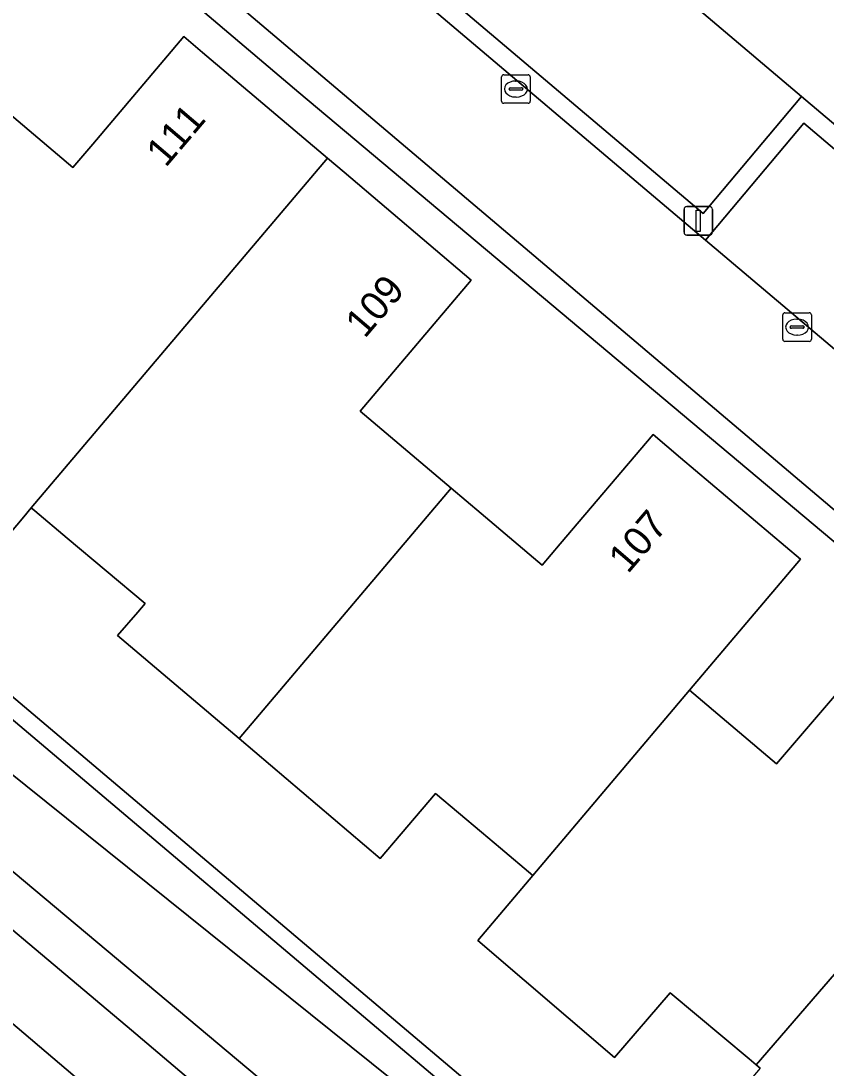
# Model space of a CAD drawing. Extents: x 156412 to 157779, y 382335 to 383768.
# Drawn here: x 156946.93 to 156975.09, y 382535.79 to 382572.44 of the extents above; entities that cross this region are included whole.
import ezdxf

# ---------------------------------------------------------------- set-up
doc = ezdxf.new("R2010")
doc.units = 0
for name, color, linetype in [('IMGEO_Erf', 7, 'Continuous'), ('IMGEO_Groenvoorziening', 7, 'Continuous'), ('IMGEO_Haag', 7, 'Continuous'), ('IMGEO_Kolk', 7, 'Continuous'), ('IMGEO_Lichtmast', 7, 'Continuous'), ('IMGEO_Oever', 7, 'Continuous'), ('IMGEO_Pand', 7, 'Continuous'), ('IMGEO_Pand_nummerreeks', 7, 'Continuous'), ('IMGEO_Parkeervlak_open', 7, 'Continuous'), ('IMGEO_Rijbaan_lokaal_open', 7, 'Continuous'), ('IMGEO_Voetpad_open', 7, 'Continuous'), ('IMGEO_Waterloop', 7, 'Continuous')]:
    doc.layers.add(name, color=color, linetype=linetype)

msp = doc.modelspace()

# ---------------------------------------------------------------- linework, layer by layer
at = {"layer": 'IMGEO_Erf'}
for points in [[(157032.018, 382606.037), (157033.314, 382604.947), (157032.946, 382604.52), (157041.703, 382597.123), (157047.972, 382604.539), (157048.196, 382604.798), (157060.586, 382619.348), (157029.826, 382645.416), (156987.205, 382681.476), (156986.214, 382682.315), (156984.143, 382684.067), (156942.915, 382635.543), (156901.626, 382586.899), (156977.949, 382522.266), (156980.608, 382525.348), (156995.995, 382543.705), (156987.057, 382551.292)], [(156985.096, 382551.062), (156984.751, 382551.362), (156982.188, 382548.489), (156956.652, 382569.938), (156926.325, 382595.645), (156936.95, 382608.202), (156992.775, 382560.898), (156990.241, 382557.869), (156990.622, 382557.547)], [(156946.128, 382569.514), (156948.739, 382567.303), (156949.437, 382568.128), (156952.622, 382571.89), (156953.277, 382571.336), (156957.652, 382567.631), (156958.23, 382567.141), (156962.681, 382563.371), (156958.797, 382558.785), (156961.981, 382556.088), (156963.032, 382555.198), (156965.165, 382553.392), (156965.795, 382554.134), (156969.046, 382557.96), (156970.005, 382557.148), (156974.199, 382553.6), (156970.317, 382549.012), (156973.355, 382546.442), (156976.505, 382550.113), (156977.268, 382551.003), (156982.117, 382546.872), (156985.394, 382550.663), (156991.994, 382545.054), (156977.449, 382527.892)], [(156972.786, 382535.791), (156972.643, 382535.912), (156972.401, 382536.118), (156969.636, 382538.426), (156967.697, 382536.158), (156962.908, 382540.256), (156964.837, 382542.536), (156963.701, 382543.486), (156963.042, 382544.044), (156961.425, 382545.397), (156960.231, 382543.992), (156959.498, 382543.128), (156954.557, 382547.323), (156950.307, 382550.931), (156951.01, 382551.743), (156951.277, 382552.051), (156948.547, 382554.34), (156947.415, 382555.289), (156947.289, 382555.394), (156947.03, 382555.088), (156946.346, 382554.281)]]:
    msp.add_lwpolyline(points, dxfattribs=at)
at = {"layer": 'IMGEO_Groenvoorziening'}
for points in [[(156975.056, 382695.155), (156974.339, 382694.322), (156973.623, 382693.49), (156976.375, 382691.256), (156980.161, 382688.027), (156981.799, 382686.639), (156940.772, 382637.701), (156895.927, 382586.799), (156991.196, 382510.245), (156996.315, 382506.277), (156998.499, 382508.854)], [(157000.033, 382540.277), (156996.653, 382543.146), (156996.633, 382543.163), (156996.382, 382542.842), (156978.115, 382521.345), (156900.751, 382586.801), (156984.174, 382685.107)], [(156982.943, 382562.429), (156974.229, 382569.798), (156970.799, 382565.697), (156960.828, 382574.147), (156964.288, 382578.231), (156963.775, 382578.659), (156959.881, 382574.086), (156970.874, 382564.762), (156974.312, 382568.857), (156982.37, 382562.02), (156978.916, 382557.959)]]:
    msp.add_lwpolyline(points, dxfattribs=at)
for points in [[(156895.927, 382586.799), (156940.772, 382637.701), (156981.799, 382686.639), (156980.161, 382688.027), (156972.98, 382679.885), (156951.724, 382654.157), (156930.591, 382629.503), (156894.284, 382586.815), (156936.438, 382551.218), (156974.72, 382519.113), (156990.891, 382505.312), (156993.571, 382503.037), (156996.315, 382506.277), (156991.196, 382510.245)], [(156984.143, 382684.067), (156986.214, 382682.315), (156986.444, 382682.612), (156986.719, 382682.899), (156984.174, 382685.107), (156900.751, 382586.801), (156978.115, 382521.345), (156996.382, 382542.842), (156996.633, 382543.163), (156995.995, 382543.705), (156980.608, 382525.348), (156977.949, 382522.266), (156901.626, 382586.899), (156942.915, 382635.543)]]:
    msp.add_lwpolyline(points, close=True, dxfattribs=at)
at = {"layer": 'IMGEO_Haag'}
msp.add_lwpolyline([(156984.143, 382684.067), (156986.214, 382682.315), (156986.444, 382682.612), (156986.719, 382682.899), (156984.174, 382685.107), (156900.751, 382586.801), (156978.115, 382521.345), (156996.382, 382542.842), (156996.633, 382543.163), (156995.995, 382543.705), (156980.608, 382525.348), (156977.949, 382522.266), (156901.626, 382586.899), (156942.915, 382635.543)], close=True, dxfattribs=at)
at = {"layer": 'IMGEO_Kolk'}
for p, q in [((156963.742, 382569.629), (156963.742, 382570.481)), ((156963.817, 382570.555), (156964.669, 382570.555)), ((156964.23, 382570.335), (156964.255, 382570.335)), ((156964.743, 382570.481), (156964.743, 382569.629)), ((156964.001, 382570.049), (156964.001, 382570.061)), ((156964.439, 382570.012), (156964.041, 382570.012)), ((156964.044, 382570.098), (156964.442, 382570.098)), ((156964.485, 382570.061), (156964.485, 382570.049)), ((156964.669, 382569.555), (156963.817, 382569.555)), ((156964.253, 382569.775), (156964.228, 382569.775)), ((156973.654, 382562.224), (156974.506, 382562.224)), ((156973.579, 382561.298), (156973.579, 382562.15)), ((156974.067, 382562.004), (156974.092, 382562.004)), ((156974.58, 382562.15), (156974.58, 382561.298)), ((156973.838, 382561.718), (156973.838, 382561.73)), ((156974.276, 382561.681), (156973.878, 382561.681)), ((156973.881, 382561.767), (156974.279, 382561.767)), ((156974.322, 382561.73), (156974.322, 382561.718)), ((156974.506, 382561.224), (156973.654, 382561.224)), ((156974.09, 382561.444), (156974.065, 382561.444))]:
    msp.add_line(p, q, dxfattribs=at)
for points in [[(156963.742, 382569.629), (156963.742, 382570.481)], [(156963.817, 382570.555), (156964.669, 382570.555)], [(156964.743, 382570.481), (156964.743, 382569.629)], [(156964.669, 382569.555), (156963.817, 382569.555)], [(156973.654, 382562.224), (156974.506, 382562.224)], [(156973.579, 382561.298), (156973.579, 382562.15)], [(156974.58, 382562.15), (156974.58, 382561.298)], [(156974.506, 382561.224), (156973.654, 382561.224)]]:
    msp.add_lwpolyline(points, dxfattribs=at)
for centre, radius, start, end in [((156963.819, 382570.479), 0.0765, 91.552, 178.448), ((156963.819, 382570.479), 0.0765, 91.552, 178.448), ((156964.667, 382570.479), 0.0765, 1.552, 88.448), ((156964.667, 382570.479), 0.0765, 1.552, 88.448), ((156964.041, 382570.058), 0.0403, 85.8775, 175.7526), ((156964.038, 382570.048), 0.0366, 178.938, 274.7102), ((156964.442, 382570.055), 0.043, 264.8664, 352.4533), ((156964.446, 382570.06), 0.0386, 1.7309, 96.639), ((156963.819, 382569.631), 0.0765, 181.552, 268.448), ((156963.819, 382569.631), 0.0765, 181.552, 268.448), ((156964.667, 382569.631), 0.0765, 271.552, 358.448), ((156964.667, 382569.631), 0.0765, 271.552, 358.448), ((156973.656, 382562.148), 0.0765, 91.552, 178.448), ((156973.656, 382562.148), 0.0765, 91.552, 178.448), ((156974.504, 382562.148), 0.0765, 1.552, 88.448), ((156974.504, 382562.148), 0.0765, 1.552, 88.448), ((156973.878, 382561.727), 0.0403, 85.8775, 175.7526), ((156973.875, 382561.717), 0.0366, 178.938, 274.7102), ((156974.279, 382561.724), 0.043, 264.8664, 352.4533), ((156974.283, 382561.729), 0.0386, 1.7309, 96.639), ((156973.656, 382561.3), 0.0765, 181.552, 268.448), ((156973.656, 382561.3), 0.0765, 181.552, 268.448), ((156974.504, 382561.3), 0.0765, 271.552, 358.448), ((156974.504, 382561.3), 0.0765, 271.552, 358.448)]:
    msp.add_arc(centre, radius, start, end, dxfattribs=at)
for centre, major_axis, ratio, start_param, end_param in [((156964.229, 382570.055), (-0.387, 0.002), 0.722429, 4.712389, 7.853982), ((156964.254, 382570.055), (-0.39, 0.002), 0.717154, 1.570796, 4.712389), ((156974.066, 382561.724), (-0.387, 0.002), 0.722429, 4.712389, 7.853982), ((156974.091, 382561.724), (-0.39, 0.002), 0.717154, 1.570796, 4.712389)]:
    msp.add_ellipse(centre, major_axis=major_axis, ratio=ratio, start_param=start_param, end_param=end_param, dxfattribs=at)
at = {"layer": 'IMGEO_Lichtmast'}
for p, q in [((156970.224, 382565.942), (156971.014, 382565.942)), ((156971.014, 382565.942), (156970.224, 382565.942)), ((156970.124, 382565.042), (156970.124, 382565.842)), ((156970.124, 382565.842), (156970.124, 382565.042)), ((156971.114, 382565.842), (156971.114, 382565.042)), ((156971.114, 382565.042), (156971.114, 382565.842)), ((156971.014, 382564.942), (156970.224, 382564.942)), ((156970.224, 382564.942), (156971.014, 382564.942))]:
    msp.add_line(p, q, dxfattribs=at)
msp.add_lwpolyline([(156970.544, 382565.817), (156970.694, 382565.817), (156970.694, 382565.067), (156970.544, 382565.067), (156970.544, 382565.817)], dxfattribs=at)
for centre, start, end in [((156970.224, 382565.842), 90, 180), ((156970.224, 382565.842), 90, 180), ((156971.014, 382565.842), 0, 90), ((156971.014, 382565.842), 360, 90), ((156970.224, 382565.042), 180, 270), ((156970.224, 382565.042), 180, 270), ((156971.014, 382565.042), 270, 0), ((156971.014, 382565.042), 270, 0)]:
    msp.add_arc(centre, 0.1, start, end, dxfattribs=at)
at = {"layer": 'IMGEO_Oever'}
for points in [[(156936.438, 382551.218), (156894.284, 382586.815), (156930.591, 382629.503), (156951.724, 382654.157), (156972.98, 382679.885), (156980.161, 382688.027), (156976.375, 382691.256), (156969.261, 382683.807), (156947.927, 382660.436), (156913.451, 382619.915), (156885.563, 382585.876), (156989.121, 382497.781), (156991.294, 382500.35), (156993.571, 382503.037), (156990.891, 382505.312), (156974.72, 382519.113)], [(156976.651, 382689.094), (156978.605, 382687.65), (156967.14, 382674.699), (156944.082, 382646.376), (156913.254, 382611.005), (156892.83, 382586.334), (156911.895, 382569.901), (156950.791, 382537.119), (156990.282, 382503.616), (156988.286, 382501.918), (156974.953, 382513.255), (156917.84, 382561.833), (156888.498, 382585.952), (156897.458, 382595.718), (156919.284, 382621.196), (156938.817, 382644.211)]]:
    msp.add_lwpolyline(points, close=True, dxfattribs=at)
at = {"layer": 'IMGEO_Pand'}
for points in [[(156957.652, 382567.631), (156953.277, 382571.336), (156952.622, 382571.89), (156949.437, 382568.128), (156948.739, 382567.303), (156946.128, 382569.514), (156945.523, 382570.026), (156938.762, 382562.039), (156938.104, 382561.262), (156937.477, 382560.522), (156941.039, 382557.486), (156941.671, 382558.233), (156946.346, 382554.281), (156947.03, 382555.088), (156947.289, 382555.394)], [(156957.652, 382567.631), (156947.289, 382555.394), (156947.415, 382555.289), (156948.547, 382554.34), (156951.277, 382552.051), (156951.01, 382551.743), (156950.307, 382550.931), (156954.557, 382547.323), (156955.269, 382548.163), (156961.981, 382556.088), (156958.797, 382558.785), (156962.681, 382563.371), (156958.23, 382567.141)], [(156961.981, 382556.088), (156955.269, 382548.163), (156954.557, 382547.323), (156959.498, 382543.128), (156960.231, 382543.992), (156961.425, 382545.397), (156963.042, 382544.044), (156963.701, 382543.486), (156964.837, 382542.536), (156970.317, 382549.012), (156974.199, 382553.6), (156970.005, 382557.148), (156969.046, 382557.96), (156965.795, 382554.134), (156965.165, 382553.392), (156963.032, 382555.198)], [(156982.117, 382546.872), (156977.268, 382551.003), (156976.505, 382550.113), (156973.355, 382546.442), (156970.317, 382549.012), (156964.837, 382542.536), (156962.908, 382540.256), (156967.697, 382536.158), (156969.636, 382538.426), (156972.401, 382536.118), (156972.643, 382535.912)], [(156991.994, 382545.054), (156985.394, 382550.663), (156982.117, 382546.872), (156972.643, 382535.912), (156972.786, 382535.791), (156970.862, 382533.51), (156977.449, 382527.892)]]:
    msp.add_lwpolyline(points, close=True, dxfattribs=at)
at = {"layer": 'IMGEO_Parkeervlak_open'}
for points in [[(156964.288, 382578.231), (156960.828, 382574.147), (156970.799, 382565.697), (156974.229, 382569.798)], [(156974.312, 382568.857), (156970.874, 382564.762), (156978.916, 382557.959), (156982.37, 382562.02)]]:
    msp.add_lwpolyline(points, close=True, dxfattribs=at)
at = {"layer": 'IMGEO_Rijbaan_lokaal_open'}
for points in [[(156989.555, 382557.259), (156988.981, 382557.799), (156991.519, 382560.783), (156937.011, 382606.884), (156927.619, 382595.781), (156982.077, 382549.644), (156984.601, 382552.665), (156985.195, 382552.172)], [(156940.534, 382598.354), (156948.462, 382591.639), (156959.455, 382582.302), (156963.775, 382578.659), (156964.288, 382578.231), (156974.229, 382569.798), (156982.943, 382562.429)], [(156978.916, 382557.959), (156970.874, 382564.762), (156959.881, 382574.086), (156955.55, 382577.733), (156955.026, 382578.17), (156945.091, 382586.598), (156936.546, 382593.826)]]:
    msp.add_lwpolyline(points, dxfattribs=at)
at = {"layer": 'IMGEO_Voetpad_open'}
for points in [[(156990.622, 382557.547), (156990.241, 382557.869), (156992.775, 382560.898), (156936.95, 382608.202), (156926.325, 382595.645), (156956.652, 382569.938), (156982.188, 382548.489), (156984.751, 382551.362), (156985.096, 382551.062)], [(156985.195, 382552.172), (156984.601, 382552.665), (156982.077, 382549.644), (156927.619, 382595.781), (156937.011, 382606.884)]]:
    msp.add_lwpolyline(points, dxfattribs=at)
at = {"layer": 'IMGEO_Waterloop'}
msp.add_lwpolyline([(156976.651, 382689.094), (156938.817, 382644.211), (156919.284, 382621.196), (156897.458, 382595.718), (156888.498, 382585.952), (156917.84, 382561.833), (156974.953, 382513.255), (156988.286, 382501.918), (156990.282, 382503.616), (156950.791, 382537.119), (156911.895, 382569.901), (156892.83, 382586.334), (156913.254, 382611.005), (156944.082, 382646.376), (156967.14, 382674.699), (156978.605, 382687.65)], close=True, dxfattribs=at)

# ---------------------------------------------------------------- texts
at = {"layer": 'IMGEO_Pand_nummerreeks'}
for s, rotation, p in [('111', 49.5551, (156951.989, 382567.28)), ('109', 49.5379, (156958.952, 382561.296)), ('107', 49.452, (156968.16, 382553.063))]:
    msp.add_text(s, height=1, rotation=rotation, dxfattribs=at).set_placement(p)

doc.saveas('drawing.dxf')
